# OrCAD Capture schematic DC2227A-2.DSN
size A3; title: 58VIN, 6A CVCC STEP-DOWN µMODULE REGULATOR; rev: 2; note: DEMO CIRCUIT 2227A
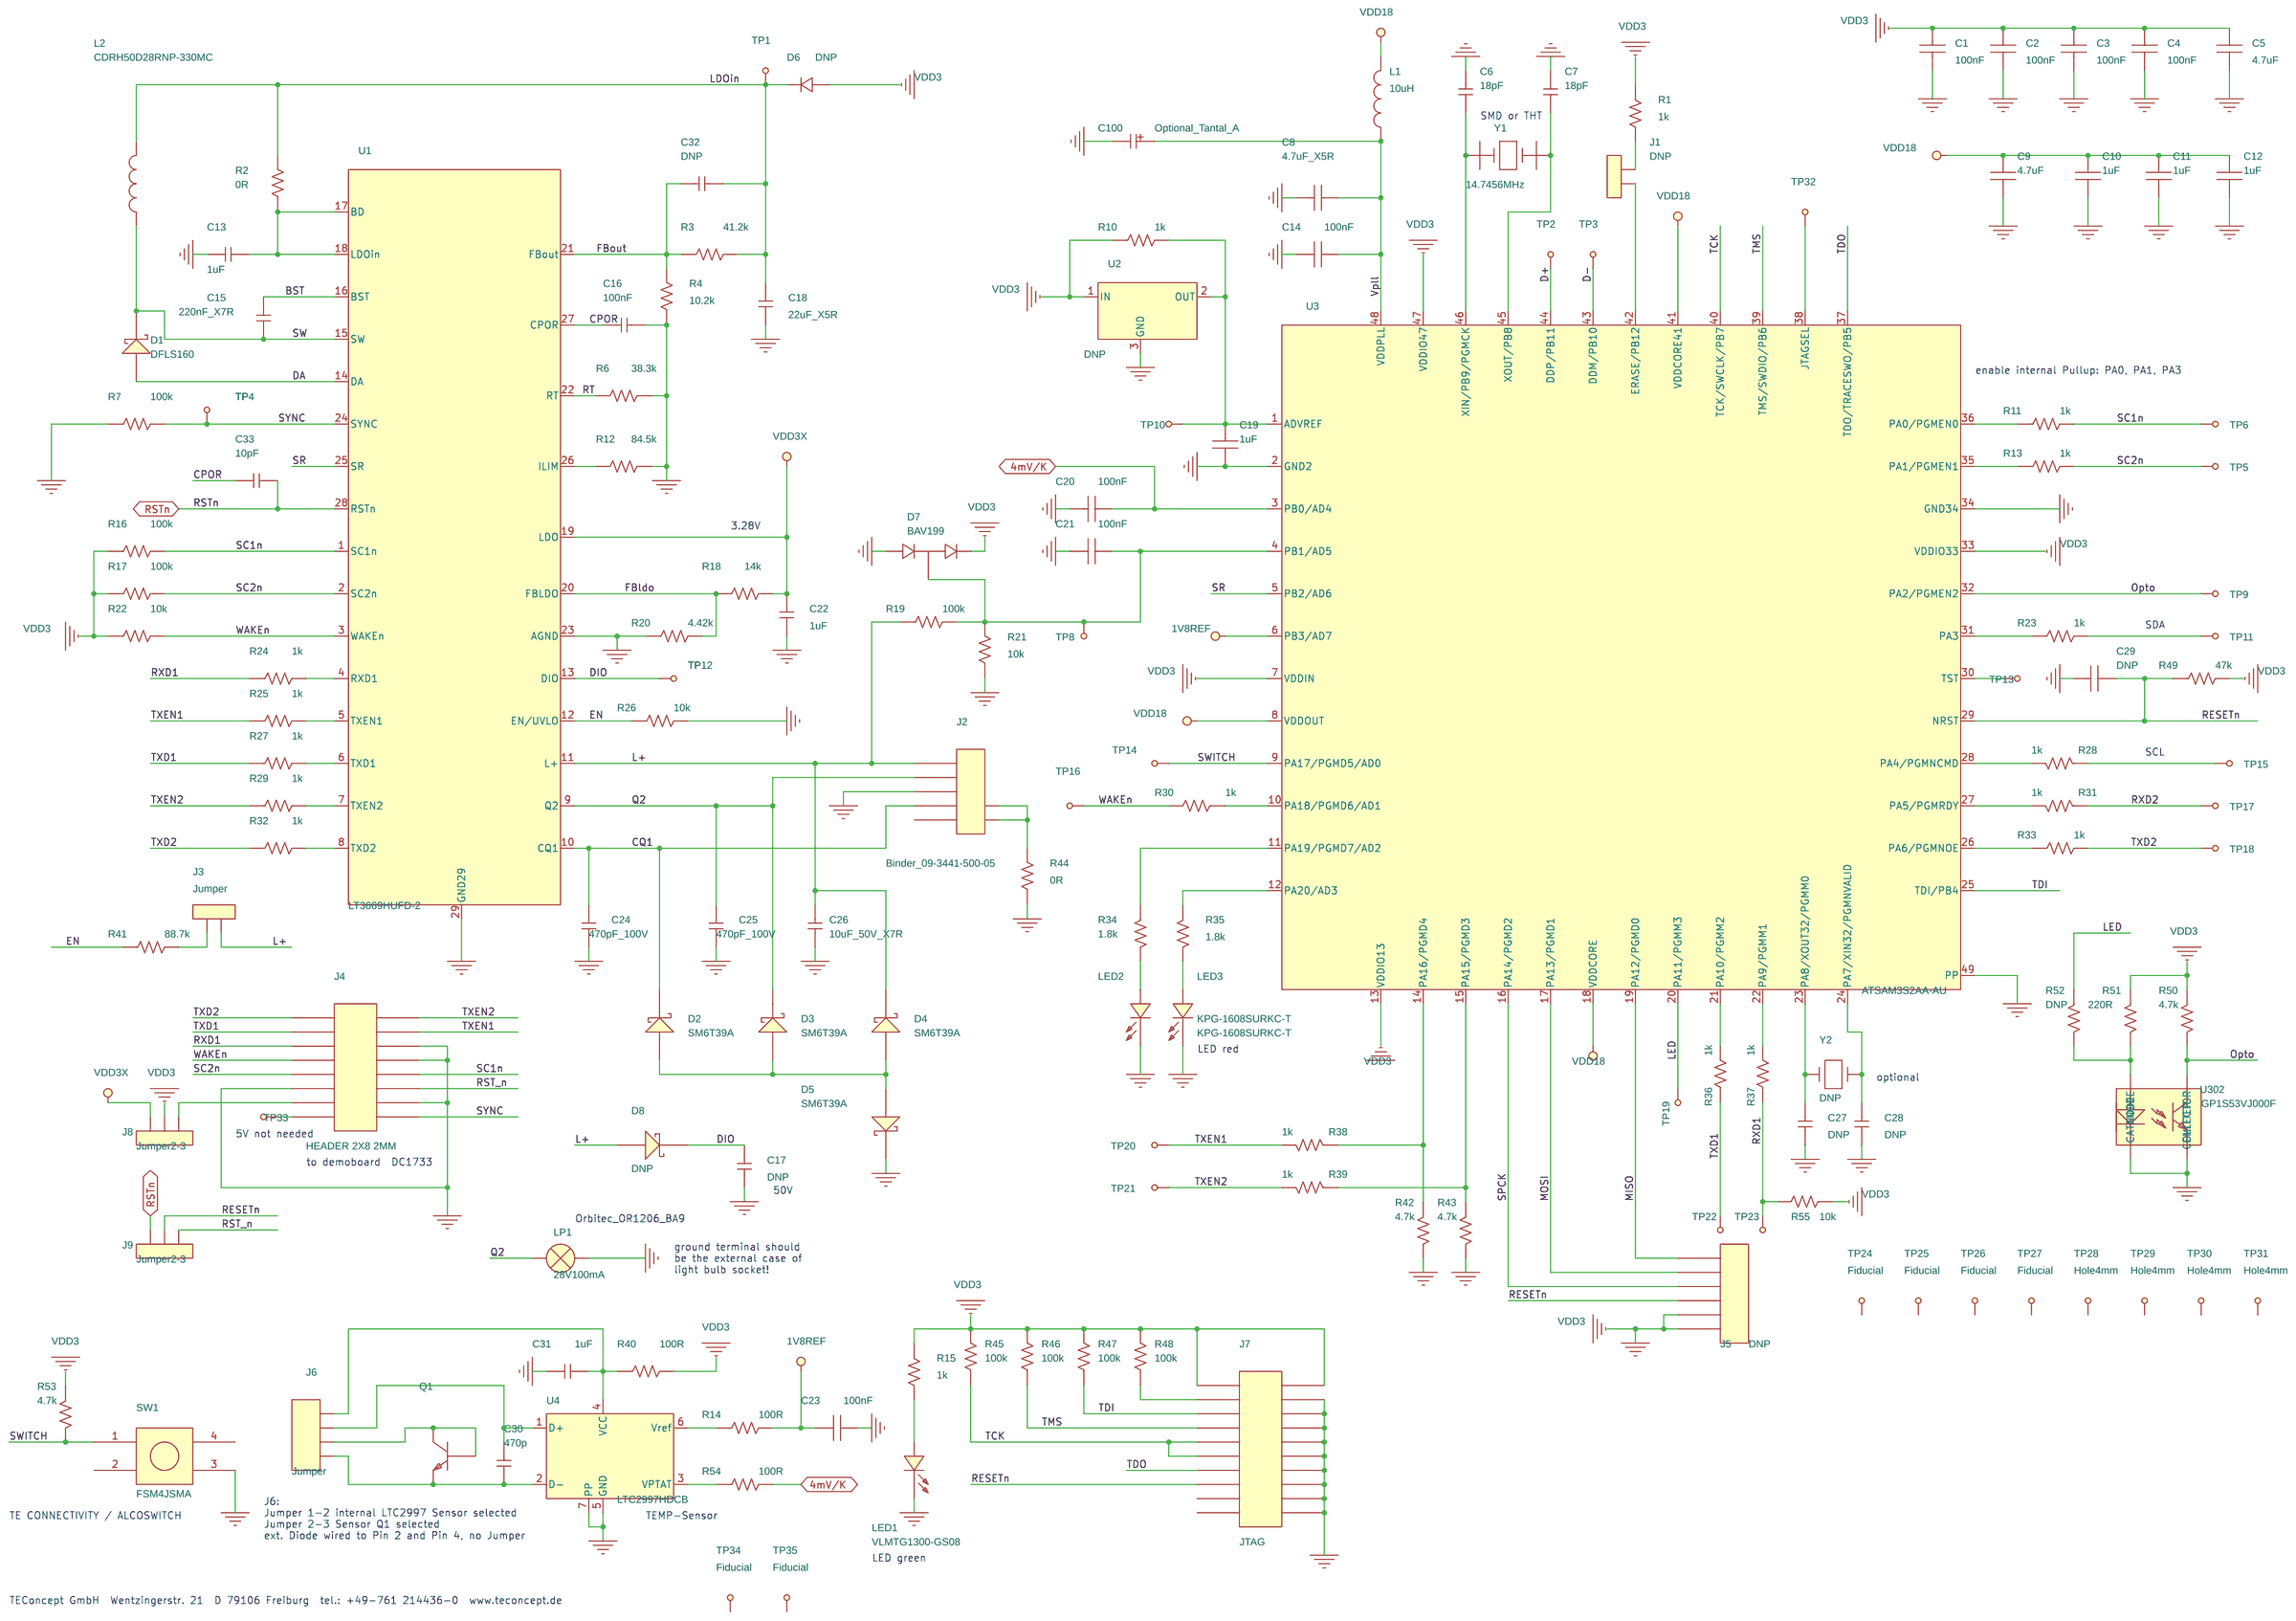
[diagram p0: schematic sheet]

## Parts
C1  100nF  [SMD_0603]
C2  100nF  [SMD_0603]
C3  100nF  [SMD_0603]
C4  100nF  [SMD_0603]
C5  4.7uF  [SMD_0805]
C6  18pF  [SMD_0603]
C7  18pF  [SMD_0603]
C8  4.7uF_X5R  [SMD_0805]
C9  4.7uF  [SMD_0805]
C10  1uF  [SMD_0603]
C11  1uF  [SMD_0603]
C12  1uF  [SMD_0603]
C13  1uF  [SMD_0603]
C14  100nF  [SMD_0603]
C15  220nF_X7R  [SMD_0603]
C16  100nF  [SMD_0603]
C17  DNP  [SMD_1206]
C18  22uF_X5R  [SMD_1206]
C19  1uF  [SMD_0603]
C20  100nF  [SMD_0603]
C21  100nF  [SMD_0603]
C22  1uF  [SMD_0603]
C23  100nF  [SMD_0603]
C24  470pF_100V  [SMD_0603]
C25  470pF_100V  [SMD_0603]
C26  10uF_50V_X7R  [SMD_1206]
C27  DNP  [SMD_0603]
C28  DNP  [SMD_0603]
C29  DNP  [SMD_0603]
C30  470p  [SMD_0603]
C31  1uF  [SMD_0603]
C32  DNP  [SMD_0603]
C33  10pF  [SMD_0603]
C100  Optional_Tantal_A  [smd_tantal_a]
D1  DFLS160  [PowerDI123]
D2  SM6T39A  [SMB]
D3  SM6T39A  [SMB]
D4  SM6T39A  [SMB]
D5  SM6T39A  [SMB]
D6  DNP  [SOD-123ex]
D7  BAV199  [SOT23]
D8  DNP  [PowerDI123]
J1  DNP  [STIFT-2_GERADE]
J2  Binder_09-3441-500-05  [Binder_09-3441-500-05]
J3  Jumper  [STIFT-2_GERADE]
J4  HEADER 2X8 2MM  [Header8x2_2mm]
J5  DNP  [STIFT-6_GERADE]
J6  Jumper  [STIFT-4_GERADE]
J7  JTAG  [header10x2]
J8  Jumper2-3  [STIFT-3_GERADE]
J9  Jumper2-3  [STIFT-3_GERADE]
L1  10uH  [SMD_0805]
L2  CDRH50D28RNP-330MC  [SMD_6x6]
LED1  VLMTG1300-GS08  [smd_0603D]
LED2  KPG-1608SURKC-T  [smd_0603D]
LED3  KPG-1608SURKC-T  [smd_0603D]
LP1  28V100mA  [Socket_BA9]
Q1  MMBT3904  [SOT23]
R1  1k  [SMD_0603]
R2  0R  [SMD_0603]
R3  41.2k  [SMD_0603]
R4  10.2k  [SMD_0603]
R6  38.3k  [SMD_0603]
R7  100k  [SMD_0603]
R10  1k  [SMD_0603]
R11  1k  [SMD_0603]
R12  84.5k  [SMD_0603]
R13  1k  [SMD_0603]
R14  100R  [SMD_0603]
R15  1k  [SMD_0603]
R16  100k  [SMD_0603]
R17  100k  [SMD_0603]
R18  14k  [SMD_0603]
R19  100k  [SMD_0603]
R20  4.42k  [SMD_0603]
R21  10k  [SMD_0603]
R22  10k  [SMD_0603]
R23  1k  [SMD_0603]
R24  1k  [SMD_0603]
R25  1k  [SMD_0603]
R26  10k  [SMD_0603]
R27  1k  [SMD_0603]
R28  1k  [SMD_0603]
R29  1k  [SMD_0603]
R30  1k  [SMD_0603]
R31  1k  [SMD_0603]
R32  1k  [SMD_0603]
R33  1k  [SMD_0603]
R34  1.8k  [SMD_0603]
R35  1.8k  [SMD_0603]
R36  1k  [SMD_0603]
R37  1k  [SMD_0603]
R38  1k  [SMD_0603]
R39  1k  [SMD_0603]
R40  100R  [SMD_0603]
R41  88.7k  [SMD_0603]
R42  4.7k  [SMD_0603]
R43  4.7k  [SMD_0603]
R44  0R  [SMD_0603]
R45  100k  [SMD_0603]
R46  100k  [SMD_0603]
R47  100k  [SMD_0603]
R48  100k  [SMD_0603]
R49  47k  [SMD_0603]
R50  4.7k  [SMD_0603]
R51  220R  [SMD_0603]
R52  DNP  [SMD_0603]
R53  4.7k  [SMD_0603]
R54  100R  [SMD_0603]
R55  10k  [SMD_0603]
SW1  FSM4JSMA  [FSM4JSMA]
TP1  TP  [TP_BOT_08]
TP2  TP  [TP_BOT_08]
TP3  TP  [TP_BOT_08]
TP4  TP  [TP_BOT_08]
TP5  TP  [TP_BOT_08]
TP6  TP  [TP_BOT_08]
TP8  TP  [TP_BOT_08]
TP9  TP  [TP_BOT_08]
TP10  TP  [TP_BOT_08]
TP11  TP  [TP_BOT_08]
TP12  TP  [TP_BOT_08]
TP13  TP  [TP_BOT_08]
TP14  TP  [TP_BOT_08]
TP15  TP  [TP_BOT_08]
TP16  TP  [TP_BOT_08]
TP17  TP  [TP_BOT_08]
TP18  TP  [TP_BOT_08]
TP19  TP  [TP_BOT_08]
TP20  TP  [TP_BOT_08]
TP21  TP  [TP_BOT_08]
TP22  TP  [TP_BOT_08]
TP23  TP  [TP_BOT_08]
TP24  Fiducial  [Fiducial]
TP25  Fiducial  [Fiducial]
TP26  Fiducial  [Fiducial]
TP27  Fiducial  [Fiducial]
TP28  Hole4mm  [LochM4]
TP29  Hole4mm  [LochM4]
TP30  Hole4mm  [LochM4]
TP31  Hole4mm  [LochM4]
TP32  TP  [TP_BOT_08]
TP33  TP  [TP_BOT_08]
TP34  Fiducial  [tt]
TP35  Fiducial  [ii]
U1  LT3669HUFD-2  [QFN28]
U2  DNP  [SOT23]
U3  ATSAM3S2AA-AU  [LQFP48_7x7]
U4  LTC2997HDCB  [DFN6]
U302  GP1S53VJ000F  [GP1S53VJ000F]
Y1  14.7456MHz  [XTAL_49SMD]
Y2  DNP  [32768Hz_SMD_5mm]

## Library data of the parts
C1-C5 C8-C12 C14 C19-C21 C23 C29 = CAP_NP
C6 C7 C13 C15-C18 C22 C24-C28 C30-C33 = C
C100 = C_elect_0
D1 D8 = STPS340U_0
D2-D5 = STPS340U_3
D6 = BAT54_PLP_0
D7 = BAV99
J1 J3 = CON2_0
J2 = CON5_1
J4 = CON16A
J5 = CON6
J6 = CON4_0
J7 = CON20A
J8 J9 = CON3_0
L1 L2 = L
LED1-LED3 = LED_0
LP1 = LAMP_0
Q1 = BC846
R1-R4 R6 R7 R10-R55 = R
SW1 = BUTTON_0
TP1-TP6 TP8-TP35 = TP_0: COMPGROUP: 40
U1 = LT3669EUFD_3
U2 = REF3025AIDBZT_0
U3 = ATSAM3S2AA-AU_2
U4 = LTC2997CDCB#PBF_1
U302 = PS2801-1_SM_0
Y1 = Crystal_2: Crystal,12MHz,20ppm,15pF,OSC-7M; Manufacturer: TXC; Manufacturer Part Number: 7M12000057; Part Number: 510-00001-1; Part Type: Clock; RoHS: Yes
Y2 = Crystal: Crystal,32.768KHz,20ppm,12.5pF,OSC-9H; Manufacturer: TXC; Manufacturer Part Number: 9H03200009; Part Number: 510-00002-1; Part Type: Clock

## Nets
1V8ref: C23.2 R14.2 U3.6(PB3/AD7)
VDD3x: C22.2 J8.3 R18.2 U1.19(LDO)
VDD18: C9.1 C10.1 C11.1 C12.1 L1.2 U3.8(VDDOUT) U3.18(VDDCORE) U3.41(VDDCORE41)
0: C1.1 C1.2 C2.1 C2.2 C3.1 C3.2 C4.1 C4.2 C5.1 C5.2 C6.2 C7.2 C8.2 C9.2 C10.2 C11.2 C12.2 C13.1 C14.2 C16.2 C17.1 C18.1 C19.2 C20.2 C21.2 C22.1 C23.1 C24.1 C25.1 C26.1 C27.2 C28.2 C29.1 C31.1 C100.2 D5.2(CATHODE) D6.1 D7.1 D7.2 J2.3 J4.6 J4.8 J4.11 J4.14 J5.5 J5.6 J7.1 J7.2 J7.4 J7.6 J7.8 J7.10 J7.12 J7.14 J7.16 J7.18 J7.20 J8.2 LED1.2 LED2.2 LED3.2 LP1.2 R1.1 R4.1 R6.1 R7.1 R10.1 R12.1 R15.1 R16.1 R17.1 R20.1 R21.1 R22.1 R26.2 R40.2 R42.2 R43.2 R44.1 R45.2 R46.2 R47.2 R48.2 R49.2 R50.1 R51.1 R53.1 R55.1 SW1.3 U1.23(AGND) U1.29(GND29) U2.1(IN) U2.3(GND) U3.2(GND2) U3.7(VDDIN) U3.13(VDDIO13) U3.33(VDDIO33) U3.34(GND34) U3.47(VDDIO47) U3.49(PP) U4.5(GND) U4.7(PP) U302.2(CATHODE) U302.4(EMITTER)
4mV/K: C20.1 R54.2 U3.3(PB0/AD4)
BST: C15.2 U1.16(BST)
CPOR: C16.1 C33.1 U1.27(CPOR)
CQ1: C24.2 D2.2(CATHODE) J2.4 U1.10(CQ1)
D+: TP2.1 U3.44(DDP/PB11)
D-: TP3.1 U3.43(DDM/PB10)
DA: D1.1(ANODE) U1.14(DA)
DIO: C17.2 D8.2(CATHODE) TP12.1 U1.13(DIO)
EN: R26.1 R41.1 U1.12(EN/UVLO)
FBldo: R18.1 R20.2 U1.20(FBLDO)
FBout: C32.1 R3.1 R4.2 U1.21(FBout)
L+: C26.2 D4.2(CATHODE) D8.1(ANODE) J2.1 J3.1 R19.1 U1.11(L+)
LDOin: C18.2 C32.2 D6.2 L2.2 R2.2 R3.2 TP1.1
LED: R52.1 TP19.1 U3.20(PA11/PGMM3)
MISO: J5.1 U3.19(PA12/PGMD0)
MOSI: J5.2 U3.17(PA13/PGMD1)
Opto: R50.2 TP9.1 U3.32(PA2/PGMEN2) U302.3(COLLECTOR)
Q2: C25.2 D3.2(CATHODE) J2.2 LP1.1 U1.9(Q2)
RESETn: C29.2 J5.4 J7.15 J9.2 R49.1 U3.29(NRST)
RST_n: J4.12 J9.1
RSTn: C33.2 J9.3 U1.28(RSTn)
RT: R6.2 U1.22(RT)
RXD1: J4.5 R24.1 R37.1 R55.2 TP23.1
RXD2: R31.1 TP17.1
SC1n: J4.10 R11.2 R16.2 TP6.1 U1.1(SC1n)
SC2n: J4.9 R13.2 R17.2 TP5.1 U1.2(SC2n)
SPCK: J5.3 U3.16(PA14/PGMD2)
SR: U1.25(SR) U3.5(PB2/AD6)
SW: C15.1 D1.2(CATHODE) L2.1 U1.15(SW)
SWITCH: R53.2 SW1.1 TP14.1 U3.9(PA17/PGMD5/AD0)
SYNC: J4.16 R7.2 TP4.1 U1.24(SYNC)
TCK: J7.9 J7.11 R45.1 U3.40(TCK/SWCLK/PB7)
TDI: J7.5 R47.1 U3.25(TDI/PB4)
TDO: J7.13 U3.37(TDO/TRACESWO/PB5)
TMS: J7.7 R46.1 U3.39(TMS/SWDIO/PB6)
TXD1: J4.3 R27.1 R36.1 TP22.1
TXD2: J4.1 R32.1 R33.2 TP18.1
TXEN1: J4.4 R25.1 R38.2 TP20.1
TXEN2: J4.2 R29.1 R39.2 TP21.1
Vpll: C8.1 C14.1 C100.1 L1.1 U3.48(VDDPLL)
WAKEn: J4.7 R22.2 R30.2 TP16.1 U1.3(WAKEn)
N9616940: C13.2 R2.1 U1.17(BD) U1.18(LDOin)
N9621799: LED1.1 R15.2
N9621971: R12.2 U1.26(ILIM)
N9685212: R24.2 U1.4(RXD1)
N9687727: R25.2 U1.5(TXEN1)
N9688086: R27.2 U1.6(TXD1)
N9688447: R29.2 U1.7(TXEN2)
N9688810: R32.2 U1.8(TXD2)
N9695366: D2.1(ANODE) D3.1(ANODE) D4.1(ANODE) D5.1(ANODE)
N9841492: J1.1 R1.2
N9841612: C21.1 D7.3 R19.2 R21.2 TP8.1 U3.4(PB1/AD5)
N9841648: TP13.1 U3.30(TST)
N9841896: C19.1 R10.2 TP10.1 U2.2(OUT) U3.1(ADVREF)
N9841962: C27.1 U3.23(PA8/XOUT32/PGMM0) Y2.2(S2)
N9841974: C28.1 U3.24(PA7/XIN32/PGMNVALID) Y2.1(S1)
N9842072: TP32.1 U3.38(JTAGSEL)
N9842140: C6.1 U3.46(XIN/PB9/PGMCK) Y1.2
N9842148: R38.1 R42.1 U3.14(PA16/PGMD4)
N9842158: C7.1 U3.45(XOUT/PB8) Y1.1
N9842174: R39.1 R43.1 U3.15(PA15/PGMD3)
N9842338: R35.1 U3.12(PA20/AD3)
N9842618: J1.2 U3.42(ERASE/PB12)
N9847711: J7.3 R48.1
N9851208: J6.3 Q1.2(B) Q1.3(C)
N9851232: C31.2 J6.1 R40.1 U4.4(VCC)
N9902788: R34.1 U3.11(PA19/PGMD7/AD2)
N9947366: R36.2 U3.21(PA10/PGMM2)
N9950163: R37.2 U3.22(PA9/PGMM1)
N9970041: R33.1 U3.26(PA6/PGMNOE)
N9979169: C30.1 J6.2 U4.1(D+)
N9979619: C30.2 J6.4 Q1.1(E) U4.2(D-)
N10015503: R28.2 U3.28(PA4/PGMNCMD)
N10015953: R31.2 U3.27(PA5/PGMRDY)
N10064965: R11.1 U3.36(PA0/PGMEN0)
N10064981: R13.1 U3.35(PA1/PGMEN1)
N10067683: R23.1 U3.31(PA3)
N10103000: LED3.1 R35.2
N10103064: LED2.1 R34.2
N10114905: R28.1 TP15.1
N10122325: R30.1 U3.10(PA18/PGMD6/AD1)
N10124952: R23.2 TP11.1
N10163810: R51.2 R52.2 U302.1(ANODE)
N10290576: J4.13 J8.1
N10313161: J4.15 TP33.1
N10400100: J3.2 R41.2
N10414247: J2.6 J2.7 R44.2
N10506519: R54.1 U4.3(VPTAT)
N10541946: R14.1 U4.6(Vref)

Not connected (* = marked no-connect by the designer): J2 5; J7 17 19; SW1 2 4; TP24 1; TP25 1; TP26 1; TP27 1; TP28 1; TP29 1; TP30 1; TP31 1; TP34 1; TP35 1

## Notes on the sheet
- SMD or THT
- enable internal Pullup: PA0, PA1, PA3
- 3.28V
- SDA
- SCL
- LED red
- optional
- 5V not needed
- to demoboard  DC1733
- 50V
- Orbitec_OR1206_BA9
- ground terminal should
  be the external case of
  light bulb socket!
- J6:
  Jumper 1-2 internal LTC2997 Sensor selected
  Jumper 2-3 Sensor Q1 selected
  ext. Diode wired to Pin 2 and Pin 4, no Jumper
- TE CONNECTIVITY / ALCOSWITCH
- TEMP-Sensor
- LED green
- TEConcept GmbH  Wentzingerstr. 21  D 79106 Freiburg  tel.: +49-761 214436-0  www.teconcept.de
